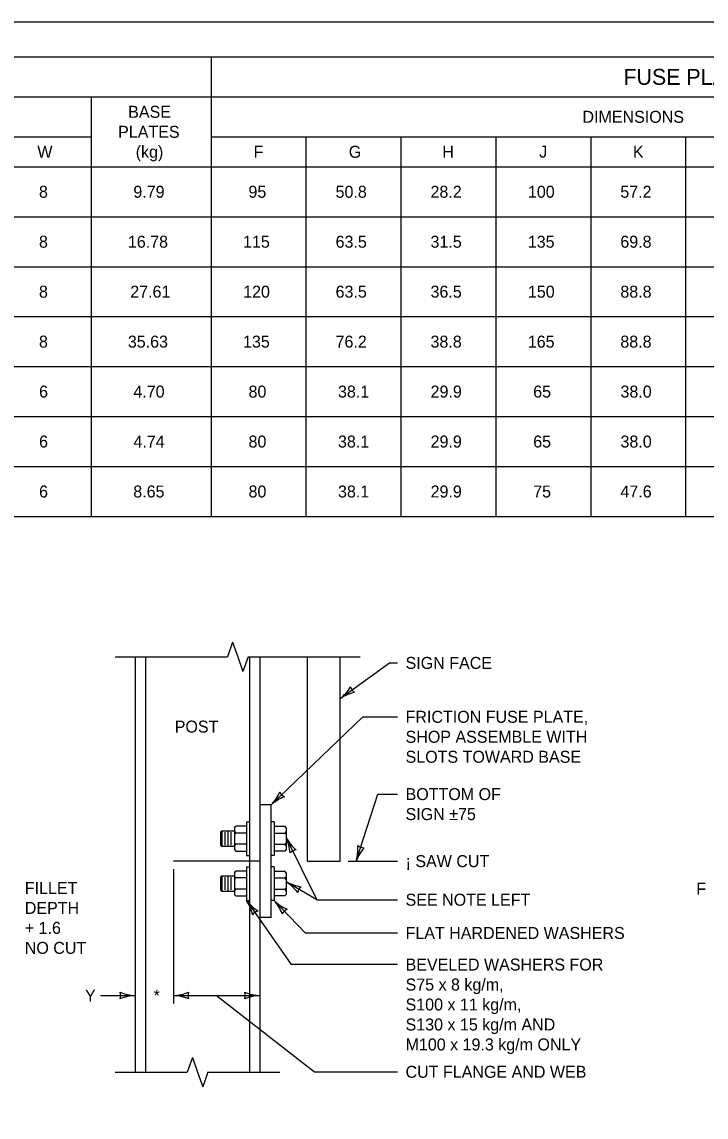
# Model space of a CAD drawing. Extents: x 49991.4 to 50021, y 49987.6 to 50011.4.
# Drawn here: x 50007.95 to 50011.38, y 49993.52 to 49999 of the extents above; entities that cross this region are included whole.
import ezdxf

# ---------------------------------------------------------------- set-up
doc = ezdxf.new("R2010")
doc.units = 0
for name, color, linetype in [('Level 1', 7, 'Continuous'), ('Level 2', 7, 'Continuous'), ('Level 3', 7, 'Continuous'), ('Level 6', 7, 'Continuous')]:
    doc.layers.add(name, color=color, linetype=linetype)

msp = doc.modelspace()

# ---------------------------------------------------------------- linework, layer by layer
at = {"layer": 'Level 1'}
for p, q in [((50008.5183, 49995.8214), (50008.5183, 49993.7433)), ((50008.57, 49995.8214), (50008.57, 49993.7433)), ((50009.0906, 49995.8214), (50009.0906, 49993.7433)), ((50009.1423, 49995.8214), (50009.1423, 49993.7433)), ((50009.3802, 49994.7994), (50009.3802, 49995.8214)), ((50009.5442, 49994.7994), (50009.5442, 49995.8214)), ((50009.1986, 49995.0807), (50009.1423, 49995.0807)), ((50009.1986, 49994.5182), (50009.1986, 49995.0807)), ((50009.0148, 49994.9664), (50009.0222, 49994.9739)), ((50009.0756, 49994.9739), (50009.0222, 49994.9739)), ((50009.0756, 49994.9964), (50009.0756, 49994.8276)), ((50009.0756, 49994.9964), (50009.0906, 49994.9964)), ((50009.2136, 49994.9964), (50009.1986, 49994.9964)), ((50009.2136, 49994.9964), (50009.2136, 49994.8276)), ((50009.2136, 49994.9739), (50009.267, 49994.9739)), ((50009.2744, 49994.9664), (50009.267, 49994.9739)), ((50008.9447, 49994.9439), (50008.9522, 49994.9514)), ((50008.9447, 49994.9439), (50008.9447, 49994.8801)), ((50008.9522, 49994.9514), (50009.0148, 49994.9514)), ((50008.9522, 49994.9514), (50008.9522, 49994.8726)), ((50008.9672, 49994.9439), (50008.9672, 49994.8801)), ((50008.9822, 49994.9514), (50008.9822, 49994.8726)), ((50008.9972, 49994.9439), (50008.9972, 49994.8801)), ((50009.0148, 49994.9664), (50009.0148, 49994.8576)), ((50009.0148, 49994.9476), (50009.0222, 49994.9401)), ((50009.0148, 49994.9326), (50009.0222, 49994.9401)), ((50009.0756, 49994.9401), (50009.0222, 49994.9401)), ((50009.2136, 49994.9401), (50009.267, 49994.9401)), ((50009.2744, 49994.9476), (50009.267, 49994.9401)), ((50009.2744, 49994.9326), (50009.267, 49994.9401)), ((50009.2744, 49994.9664), (50009.2744, 49994.8576)), ((50008.9447, 49994.8801), (50008.9522, 49994.8726)), ((50009.0148, 49994.8726), (50008.9522, 49994.8726)), ((50009.0148, 49994.8914), (50009.0222, 49994.8839)), ((50009.0148, 49994.8764), (50009.0222, 49994.8839)), ((50009.0756, 49994.8839), (50009.0222, 49994.8839)), ((50009.2136, 49994.8839), (50009.267, 49994.8839)), ((50009.2744, 49994.8914), (50009.267, 49994.8839)), ((50009.2744, 49994.8764), (50009.267, 49994.8839)), ((50009.0148, 49994.8576), (50009.0222, 49994.8501)), ((50009.0222, 49994.8501), (50009.0756, 49994.8501)), ((50009.0756, 49994.8276), (50009.0906, 49994.8276)), ((50009.2136, 49994.8276), (50009.1986, 49994.8276)), ((50009.267, 49994.8501), (50009.2136, 49994.8501)), ((50009.2744, 49994.8576), (50009.267, 49994.8501)), ((50009.1423, 49994.7994), (50008.7093, 49994.7994)), ((50009.0756, 49994.7714), (50009.0756, 49994.6026)), ((50009.0756, 49994.7714), (50009.0906, 49994.7714)), ((50009.2136, 49994.7714), (50009.1986, 49994.7714)), ((50009.2136, 49994.7714), (50009.2136, 49994.6026)), ((50009.3802, 49994.7994), (50009.5442, 49994.7994)), ((50008.9447, 49994.7188), (50008.9522, 49994.7264)), ((50008.9447, 49994.7188), (50008.9447, 49994.6551)), ((50008.9522, 49994.7264), (50009.0148, 49994.7264)), ((50008.9522, 49994.7264), (50008.9522, 49994.6476)), ((50008.9672, 49994.7188), (50008.9672, 49994.6551)), ((50008.9822, 49994.7264), (50008.9822, 49994.6476)), ((50008.9972, 49994.7188), (50008.9972, 49994.6551)), ((50009.0148, 49994.7414), (50009.0222, 49994.7488)), ((50009.0148, 49994.7414), (50009.0148, 49994.6326)), ((50009.0148, 49994.7226), (50009.0222, 49994.7151)), ((50009.0148, 49994.7076), (50009.0222, 49994.7151)), ((50009.0756, 49994.7488), (50009.0222, 49994.7488)), ((50009.0756, 49994.7151), (50009.0222, 49994.7151)), ((50009.2136, 49994.7488), (50009.267, 49994.7488)), ((50009.2136, 49994.7151), (50009.267, 49994.7151)), ((50009.2744, 49994.7414), (50009.267, 49994.7488)), ((50009.2744, 49994.7226), (50009.267, 49994.7151)), ((50009.2744, 49994.7076), (50009.267, 49994.7151)), ((50009.2744, 49994.7414), (50009.2744, 49994.6326)), ((50008.9447, 49994.6551), (50008.9522, 49994.6476)), ((50009.0148, 49994.6476), (50008.9522, 49994.6476)), ((50009.0148, 49994.6664), (50009.0222, 49994.6588)), ((50009.0148, 49994.6514), (50009.0222, 49994.6588)), ((50009.0756, 49994.6588), (50009.0222, 49994.6588)), ((50009.2136, 49994.6588), (50009.267, 49994.6588)), ((50009.2744, 49994.6664), (50009.267, 49994.6588)), ((50009.2744, 49994.6514), (50009.267, 49994.6588)), ((50009.0148, 49994.6326), (50009.0222, 49994.6251)), ((50009.0222, 49994.6251), (50009.0756, 49994.6251)), ((50009.0756, 49994.6026), (50009.0906, 49994.6026)), ((50009.2136, 49994.6026), (50009.1986, 49994.6026)), ((50009.267, 49994.6251), (50009.2136, 49994.6251)), ((50009.2744, 49994.6326), (50009.267, 49994.6251)), ((50009.1986, 49994.5182), (50009.1423, 49994.5182))]:
    msp.add_line(p, q, dxfattribs=at)
msp.add_lwpolyline([(49999.3835, 49998.9992), (50016.7501, 49998.9992), (50016.7501, 49987.7988), (49999.3835, 49987.7988)], close=True, dxfattribs=at)
at = {"layer": 'Level 2'}
for p, q in [((50002.7742, 49998.8242), (50016.4992, 49998.8242)), ((50008.8992, 49996.5242), (50008.8992, 49998.8242)), ((50002.7742, 49998.6242), (50016.4992, 49998.6242)), ((50008.2992, 49996.5242), (50008.2992, 49998.6242)), ((50004.9742, 49998.4242), (50008.2992, 49998.4242)), ((50008.2992, 49996.5242), (50008.2992, 49998.4242)), ((50008.8992, 49998.4242), (50013.1742, 49998.4242)), ((50009.3742, 49996.5242), (50009.3742, 49998.4242)), ((50009.8492, 49996.5242), (50009.8492, 49998.4242)), ((50010.3242, 49996.5242), (50010.3242, 49998.4242)), ((50010.7992, 49996.5242), (50010.7992, 49998.4242)), ((50011.2742, 49996.5242), (50011.2742, 49998.4242)), ((50002.7742, 49998.2742), (50016.4992, 49998.2742)), ((50004.9742, 49998.0242), (50016.4992, 49998.0242)), ((50002.7742, 49997.7742), (50016.4992, 49997.7742)), ((50004.9742, 49997.5242), (50016.4992, 49997.5242)), ((50002.7742, 49997.2742), (50016.4992, 49997.2742)), ((50004.9742, 49997.0242), (50016.4992, 49997.0242)), ((50002.7742, 49996.7742), (50016.4992, 49996.7742)), ((50002.7742, 49996.5242), (50016.4992, 49996.5242))]:
    msp.add_line(p, q, dxfattribs=at)
at = {"layer": 'Level 3'}
for p, q in [((50009.5442, 49995.6128), (50009.7912, 49995.7914)), ((50009.7912, 49995.7914), (50009.8312, 49995.7914)), ((50009.1986, 49995.0807), (50009.6571, 49995.5217)), ((50009.6571, 49995.5217), (50009.8312, 49995.5217)), ((50009.6242, 49994.7994), (50009.7327, 49995.1349)), ((50009.7327, 49995.1349), (50009.8312, 49995.1349)), ((50009.2744, 49994.9163), (50009.4273, 49994.6063)), ((50008.7093, 49994.7594), (50008.7093, 49994.0866)), ((50009.5842, 49994.7994), (50009.8312, 49994.7994)), ((50009.4273, 49994.6063), (50009.2744, 49994.6952)), ((50009.0756, 49994.6026), (50009.2984, 49994.282)), ((50009.2136, 49994.6026), (50009.3684, 49994.44)), ((50009.4273, 49994.6063), (50009.8312, 49994.6063)), ((50009.3684, 49994.44), (50009.8312, 49994.44)), ((50009.8312, 49994.282), (50009.2984, 49994.282)), ((50008.3449, 49994.1266), (50008.5183, 49994.1266)), ((50008.7093, 49994.1266), (50009.1423, 49994.1266)), ((50008.9258, 49994.1266), (50009.4149, 49993.7452)), ((50009.4149, 49993.7452), (50009.8312, 49993.7452))]:
    msp.add_line(p, q, dxfattribs=at)
for centre, radius, start, end in [((50009.3985, 49995.7946), 0.233, 308.6971, 327.947), ((50009.6669, 49995.4274), 0.2223, 103.3258, 123.5093), ((50009.6481, 49995.6879), 0.0548, 198.0086, 233.731), ((50009.029, 49995.2405), 0.233, 316.7127, 335.9626), ((50009.291, 49995.1696), 0.0548, 206.0243, 241.7466), ((50009.346, 49994.9143), 0.2223, 111.3414, 131.525), ((50009.0711, 49994.8263), 0.2223, 3.7097, 23.8932), ((50009.478, 49995.0295), 0.233, 209.081, 228.3309), ((50009.3992, 49994.8601), 0.233, 344.9062, 4.1561), ((50009.8327, 49994.7223), 0.2223, 139.5349, 159.7184), ((50009.6637, 49994.9214), 0.0548, 234.2177, 269.9401), ((50009.3311, 49994.8013), 0.0548, 98.3925, 134.1149), ((50009.1548, 49994.5078), 0.2223, 37.2812, 57.4647), ((50009.3814, 49994.9022), 0.233, 242.6525, 261.9023), ((50009.3852, 49994.6308), 0.0548, 131.964, 167.6864), ((50008.888, 49994.4833), 0.2223, 12.2581, 32.4416), ((50009.2601, 49994.7449), 0.233, 217.6294, 236.8792), ((50009.0464, 49994.4561), 0.2223, 21.0483, 41.2318), ((50009.3742, 49994.7714), 0.233, 226.4196, 245.6694), ((50009.1488, 49994.4973), 0.0548, 106.9409, 142.6632), ((50009.302, 49994.5097), 0.0548, 115.7311, 151.4534), ((50008.5275, 49994.3487), 0.2223, 247.456, 267.6395), ((50008.3901, 49994.1266), 0.0548, 342.1388, 17.8612), ((50008.5298, 49993.8939), 0.233, 92.8273, 112.0772), ((50008.6978, 49994.3593), 0.233, 272.8273, 292.0772), ((50008.7001, 49993.9045), 0.2223, 67.456, 87.6395), ((50008.8375, 49994.1266), 0.0548, 162.1388, 197.8612), ((50009.1515, 49994.3487), 0.2223, 247.456, 267.6395), ((50009.0141, 49994.1266), 0.0548, 342.1388, 17.8612), ((50009.1538, 49993.8939), 0.233, 92.8273, 112.0772)]:
    msp.add_arc(centre, radius, start, end, dxfattribs=at)
at = {"layer": 'Level 6'}
for p, q in [((50009.0053, 49995.8945), (50008.9794, 49995.8214)), ((50009.0053, 49995.8945), (50009.0312, 49995.8214)), ((50008.4183, 49995.8214), (50008.9794, 49995.8214)), ((50009.0312, 49995.8214), (50009.0571, 49995.7483)), ((50009.083, 49995.8214), (50009.0571, 49995.7483)), ((50009.083, 49995.8214), (50009.6442, 49995.8214)), ((50008.8044, 49993.8164), (50008.7785, 49993.7433)), ((50008.8044, 49993.8164), (50008.8303, 49993.7433)), ((50008.4183, 49993.7433), (50008.7785, 49993.7433)), ((50008.8303, 49993.7433), (50008.8562, 49993.6702)), ((50008.8821, 49993.7433), (50008.8562, 49993.6702)), ((50008.8821, 49993.7433), (50009.2423, 49993.7433))]:
    msp.add_line(p, q, dxfattribs=at)

# ---------------------------------------------------------------- texts
at = {"layer": 'Level 2'}
for s, height, p in [('FUSE PLATE DATA', 0.08, (50010.9615, 49998.6842)), ('BASE', 0.06, (50008.4831, 49998.5192)), ('DIMENSIONS', 0.06, (50010.7564, 49998.4942)), ('PLATES', 0.06, (50008.4328, 49998.4192)), ('W', 0.06, (50008.0285, 49998.3192)), ('(kg)', 0.06, (50008.5208, 49998.3192)), ('F', 0.06, (50009.1106, 49998.3192)), ('G', 0.06, (50009.5869, 49998.3192)), ('H', 0.06, (50010.0547, 49998.3192)), ('J', 0.06, (50010.5399, 49998.3204)), ('K', 0.06, (50011.0086, 49998.3192)), ('8', 0.06, (50008.0367, 49998.1192)), ('9.79', 0.06, (50008.509, 49998.1192)), ('95', 0.06, (50009.0849, 49998.1192)), ('50.8', 0.06, (50009.521, 49998.1192)), ('28.2', 0.06, (50009.9959, 49998.1192)), ('100', 0.06, (50010.4835, 49998.1192)), ('57.2', 0.06, (50010.9459, 49998.1192)), ('8', 0.06, (50008.0367, 49997.8692)), ('16.78', 0.06, (50008.4816, 49997.8692)), ('63.5', 0.06, (50009.5211, 49997.8692)), ('31.5', 0.06, (50009.9961, 49997.8692)), ('135', 0.06, (50010.4829, 49997.8692)), ('69.8', 0.06, (50010.946, 49997.8692)), ('115', 0.06, (50009.0579, 49997.8692)), ('8', 0.06, (50008.0367, 49997.6192)), ('27.61', 0.06, (50008.4936, 49997.6192)), ('120', 0.06, (50009.0585, 49997.6192)), ('63.5', 0.06, (50009.5211, 49997.6192)), ('36.5', 0.06, (50009.9961, 49997.6192)), ('150', 0.06, (50010.4835, 49997.6192)), ('88.8', 0.06, (50010.946, 49997.6192)), ('8', 0.06, (50008.0367, 49997.3692)), ('35.63', 0.06, (50008.4814, 49997.3692)), ('135', 0.06, (50009.0579, 49997.3692)), ('76.2', 0.06, (50009.5209, 49997.3692)), ('38.8', 0.06, (50009.996, 49997.3692)), ('165', 0.06, (50010.4829, 49997.3692)), ('88.8', 0.06, (50010.946, 49997.3692)), ('6', 0.06, (50008.0372, 49997.1192)), ('4.70', 0.06, (50008.5092, 49997.1192)), ('80', 0.06, (50009.0854, 49997.1192)), ('38.1', 0.06, (50009.5331, 49997.1192)), ('29.9', 0.06, (50009.9965, 49997.1192)), ('65', 0.06, (50010.5099, 49997.1192)), ('38.0', 0.06, (50010.9467, 49997.1192)), ('6', 0.06, (50008.0372, 49996.8692)), ('4.74', 0.06, (50008.5095, 49996.8692)), ('80', 0.06, (50009.0854, 49996.8692)), ('38.1', 0.06, (50009.5331, 49996.8692)), ('29.9', 0.06, (50009.9965, 49996.8692)), ('65', 0.06, (50010.5099, 49996.8692)), ('38.0', 0.06, (50010.9467, 49996.8692)), ('6', 0.06, (50008.0372, 49996.6192)), ('8.65', 0.06, (50008.5086, 49996.6192)), ('80', 0.06, (50009.0854, 49996.6192)), ('38.1', 0.06, (50009.5331, 49996.6192)), ('29.9', 0.06, (50009.9965, 49996.6192)), ('75', 0.06, (50010.5099, 49996.6192)), ('47.6', 0.06, (50010.9465, 49996.6192)), ('SIGN FACE', 0.06, (50009.8712, 49995.7614)), ('FRICTION FUSE PLATE,', 0.06, (50009.8712, 49995.4917)), ('POST', 0.06, (50008.716, 49995.4427)), ('SHOP ASSEMBLE WITH', 0.06, (50009.8712, 49995.3917)), ('SLOTS TOWARD BASE', 0.06, (50009.8712, 49995.2917)), ('BOTTOM OF', 0.06, (50009.8712, 49995.1049)), ('SIGN ±75', 0.06, (50009.8712, 49995.0049)), ('¡ SAW CUT', 0.06, (50009.8712, 49994.7694)), ('FILLET', 0.06, (50007.9657, 49994.6354)), ('F', 0.06, (50011.326, 49994.6315)), ('DEPTH', 0.06, (50007.9657, 49994.5354)), ('SEE NOTE LEFT', 0.06, (50009.8712, 49994.5763)), ('+ 1.6', 0.06, (50007.9657, 49994.4354)), ('FLAT HARDENED WASHERS', 0.06, (50009.8712, 49994.41)), ('NO CUT', 0.06, (50007.9657, 49994.3354)), ('BEVELED WASHERS FOR', 0.06, (50009.8712, 49994.252)), ('S75 x 8 kg/m,', 0.06, (50009.8712, 49994.152)), ('Y', 0.06, (50008.2671, 49994.0966)), ('*', 0.06, (50008.6104, 49994.0966)), ('S100 x 11 kg/m,', 0.06, (50009.8712, 49994.052)), ('S130 x 15 kg/m AND', 0.06, (50009.8712, 49993.952)), ('M100 x 19.3 kg/m ONLY', 0.06, (50009.8712, 49993.852)), ('CUT FLANGE AND WEB', 0.06, (50009.8712, 49993.7152))]:
    msp.add_text(s, height=height, dxfattribs=at).set_placement(p)

doc.saveas('drawing.dxf')
